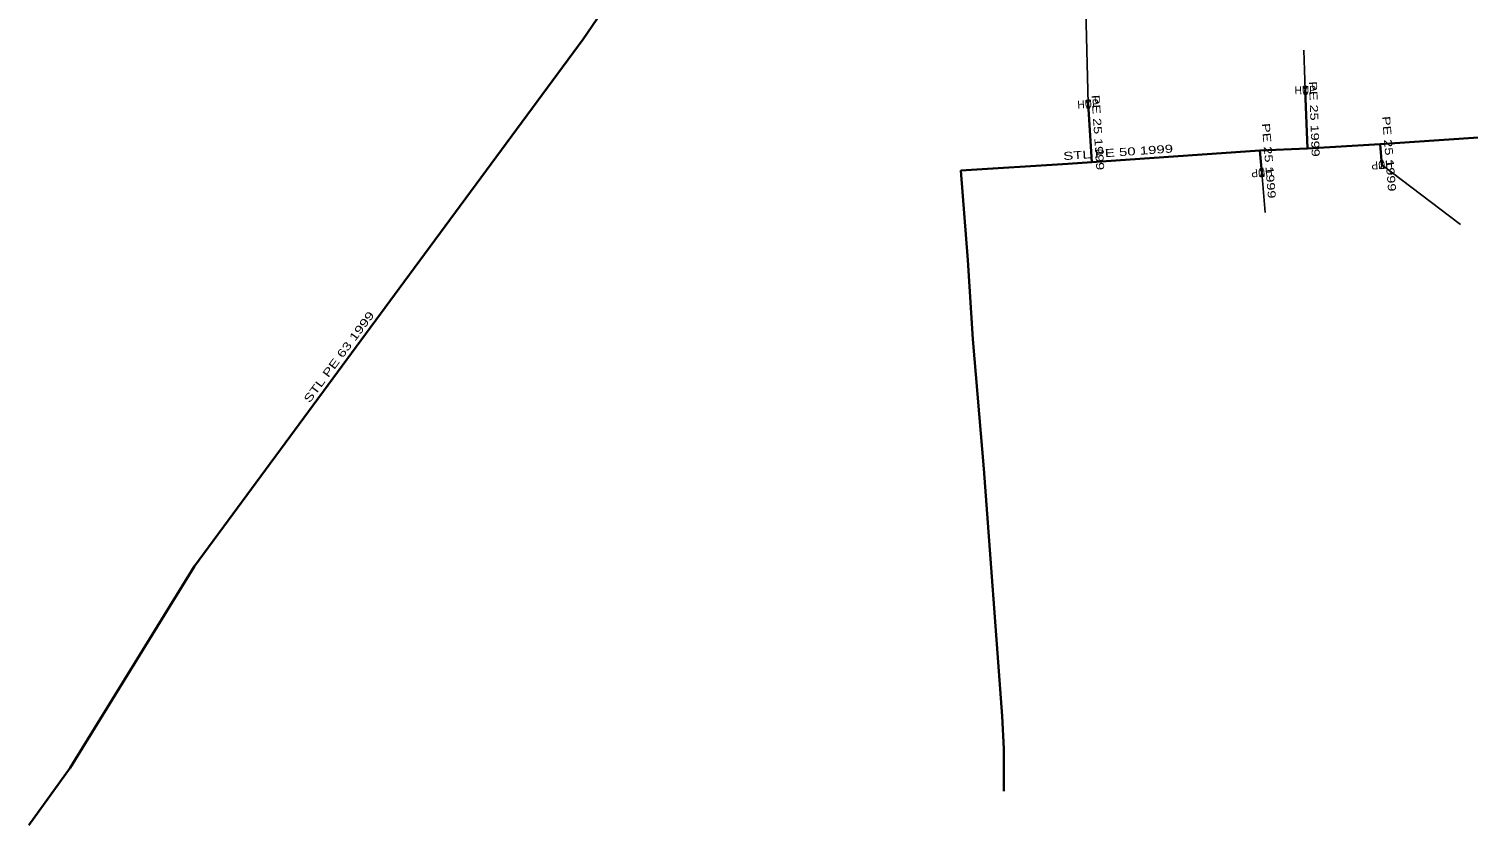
# Model space of a CAD drawing. Extents: x -737484 to -734496, y -1033882 to -1030666.
# Drawn here: x -734941.7 to -734761.8, y -1033817.9 to -1033718.3 of the extents above; entities that cross this region are included whole.
import ezdxf
from ezdxf.enums import TextEntityAlignment as Align

# ---------------------------------------------------------------- set-up
doc = ezdxf.new("R2010")
doc.units = 0
doc.header["$LTSCALE"] = 0.4
for name, color, linetype, lineweight in [('1', 7, 'Continuous', 13), ('22', 7, 'Continuous', 25), ('5', 7, 'Continuous', 35), ('7', 7, 'Continuous', 35)]:
    doc.layers.add(name, color=color, linetype=linetype, lineweight=lineweight)
doc.layers.add('2', color=7, linetype='Continuous')

msp = doc.modelspace()

# ---------------------------------------------------------------- linework, layer by layer
at = {"layer": '1'}
for points in [[(-734782.407, -1033725.496), (-734782.007, -1033725.482), (-734782.372, -1033726.495), (-734781.972, -1033726.481)], [(-734809.564, -1033727.235), (-734809.165, -1033727.207), (-734809.494, -1033728.232), (-734809.095, -1033728.204)], [(-734787.377, -1033736.779), (-734787.775, -1033736.814), (-734787.464, -1033735.783), (-734787.862, -1033735.818)], [(-734772.366, -1033735.809), (-734772.764, -1033735.844), (-734772.453, -1033734.813), (-734772.851, -1033734.848)]]:
    msp.add_lwpolyline(points, close=True, dxfattribs=at)
at = {"layer": '22'}
for p, q in [((-734809.33, -1033727.72), (-734809.839, -1033704.94)), ((-734782.19, -1033725.989), (-734782.375, -1033720.992)), ((-734772.609, -1033735.329), (-734762.816, -1033742.787)), ((-734787.62, -1033736.299), (-734787.206, -1033741.282))]:
    msp.add_line(p, q, dxfattribs=at)
at = {"layer": '5'}
for points in [[(-734941.67, -1033817.87), (-734936.52, -1033810.71), (-734920.97, -1033785.5), (-734895.38, -1033750.81), (-734872.39, -1033719.63), (-734861.07, -1033703.01)], [(-734708.19, -1033728.68), (-734722.59, -1033729.48), (-734727.88, -1033729.67), (-734747.46, -1033731), (-734748.31, -1033731.1), (-734772.82, -1033732.74), (-734781.92, -1033733.3), (-734787.85, -1033733.53), (-734808.86, -1033735), (-734811.85, -1033735.2), (-734825.21, -1033736.06), (-734824.33, -1033747.25), (-734823.73, -1033757.14), (-734822.34, -1033773.33), (-734820.07, -1033804.26), (-734819.85, -1033808.31), (-734819.87, -1033813.62)]]:
    msp.add_lwpolyline(points, dxfattribs=at)
at = {"layer": '7'}
for p, q in [((-734781.92, -1033733.3), (-734782.19, -1033725.989)), ((-734808.86, -1033735), (-734809.33, -1033727.72)), ((-734787.85, -1033733.53), (-734787.62, -1033736.299)), ((-734772.82, -1033732.74), (-734772.609, -1033735.329))]:
    msp.add_line(p, q, dxfattribs=at)

# ---------------------------------------------------------------- texts
at = {"layer": '2', "width": 0.95}
for rotation, p in [(4, (-734809.2944, -1033728.2184)), (2, (-734782.1719, -1033726.4877)), (185, (-734787.6629, -1033735.8007)), (185, (-734772.6519, -1033734.8307))]:
    msp.add_text('HUP', height=1, rotation=rotation, dxfattribs=at).set_placement(p, align=Align.CENTER)
at = {"layer": '5', "width": 1.4}
for s, rotation, p in [('STL PE 50 1999', 4.002, (-734805.5384, -1033734.2656)), ('STL PE 63 1999', 53.585, (-734902.5193, -1033759.6463))]:
    msp.add_text(s, height=1, rotation=rotation, dxfattribs=at).set_placement(p, align=Align.CENTER)
at = {"layer": '7', "width": 1.35}
for rotation, p in [(272.115, (-734781.5549, -1033729.6255)), (273.694, (-734808.5958, -1033731.3268)), (274.748, (-734787.2357, -1033734.8726)), (274.659, (-734772.2152, -1033733.9929))]:
    msp.add_text('PE 25 1999', height=1, rotation=rotation, dxfattribs=at).set_placement(p, align=Align.CENTER)

doc.saveas('drawing.dxf')
